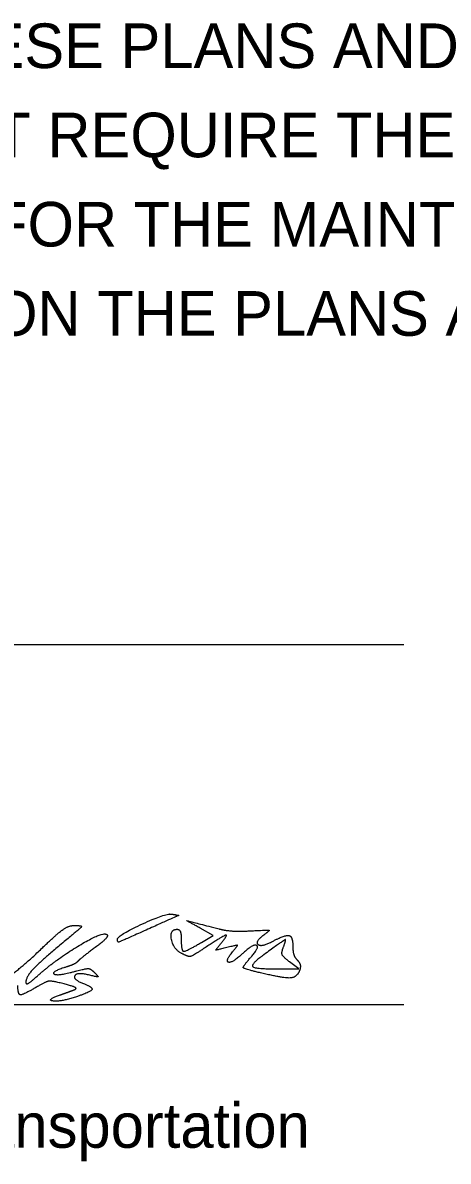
# Model space of a CAD drawing. Extents: x 0 to 34, y 0 to 22.
# Drawn here: x 26.833 to 28.167, y 7.305 to 10.877 of the extents above; entities that cross this region are included whole.
import ezdxf

# ---------------------------------------------------------------- set-up
doc = ezdxf.new("R2010")
doc.units = 0
doc.layers.add('SH_Data', color=7, linetype='Continuous')
doc.layers.add('SH_Text', color=7, linetype='Continuous')

msp = doc.modelspace()

# ---------------------------------------------------------------- linework, layer by layer
at = {"layer": 'SH_Data'}
for p, q in [((24.5279, 8.9262), (28.0279, 8.9262)), ((24.5279, 7.7968), (28.0279, 7.7968))]:
    msp.add_line(p, q, dxfattribs=at)
at = {"layer": 'SH_Text'}
for p, q in [((27.1295, 8.001), (27.1295, 8.001)), ((27.582, 7.8948), (27.582, 7.8948))]:
    msp.add_line(p, q, dxfattribs=at)
for points in [[(27.3933, 7.9914), (27.4297, 8.0129), (27.3889, 8.0359)], [(27.642, 7.9079), (27.6982, 7.908), (27.6695, 7.9301)]]:
    msp.add_lwpolyline(points, dxfattribs=at)
for points in [[(27.1295, 8.001), (27.1295, 8.0134), (27.2823, 8.0837), (27.3012, 8.08)], [(27.3012, 8.08), (27.3219, 8.076), (27.3226, 8.0764), (27.201, 8.0218)], [(26.8951, 7.9753), (26.9403, 8.019), (26.9774, 8.0447), (26.9951, 8.0444)], [(26.9951, 8.0444), (27.0194, 8.0439), (27.0156, 8.0375), (26.967, 7.9975)], [(27.3889, 8.0359), (27.3461, 8.06), (27.3452, 8.06), (27.4482, 8.0336)], [(26.8763, 7.8841), (26.93, 7.9329), (27.0769, 8.0229), (27.0938, 8.0172)], [(27.0938, 8.0172), (27.1022, 8.0144), (27.087, 7.9957), (27.0599, 7.9755)], [(27.201, 8.0218), (27.1385, 7.9937), (27.1295, 7.9911), (27.1295, 8.001)], [(27.3305, 7.9569), (27.304, 7.9711), (27.293, 8.0324), (27.317, 8.0324)], [(27.317, 8.0324), (27.3238, 8.0324), (27.3295, 8.0184), (27.3295, 8.0012)], [(27.4529, 7.9866), (27.4773, 8.0162), (27.4615, 8.0124), (27.4052, 7.9752)], [(27.4482, 8.0336), (27.4688, 8.0284), (27.5138, 8.0256), (27.5482, 8.0275)], [(27.5482, 8.0275), (27.6031, 8.0306), (27.608, 8.029), (27.5881, 8.0142)], [(27.5881, 8.0142), (27.5593, 7.9927), (27.5822, 7.9763), (27.6159, 7.9944)], [(27.6159, 7.9944), (27.6561, 8.0159), (27.6795, 8.0101), (27.6795, 7.9787)], [(26.7295, 7.8684), (26.7295, 7.8456), (26.8248, 7.907), (26.8951, 7.9753)], [(26.967, 7.9975), (26.8929, 7.9366), (26.842, 7.883), (26.842, 7.8663)], [(27.0599, 7.9755), (27.0328, 7.9553), (27.0079, 7.9353), (27.0045, 7.9311)], [(27.3295, 8.0012), (27.3295, 7.9644), (27.3438, 7.9622), (27.3933, 7.9914)], [(27.4052, 7.9752), (27.3652, 7.9487), (27.3519, 7.9454), (27.3305, 7.9569)], [(27.4723, 7.9749), (27.4392, 7.9667), (27.4374, 7.9678), (27.4529, 7.9866)], [(27.4924, 7.9642), (27.507, 7.9818), (27.5047, 7.983), (27.4723, 7.9749)], [(27.5462, 7.9428), (27.5767, 7.9764), (27.5551, 7.9874), (27.5211, 7.9554)], [(27.6497, 7.9756), (27.6596, 8.0014), (27.6514, 7.9983), (27.5888, 7.9527)], [(27.6695, 7.9301), (27.6491, 7.9458), (27.6434, 7.959), (27.6497, 7.9756)], [(27.6795, 7.9787), (27.6795, 7.9629), (27.6858, 7.9436), (27.6936, 7.9358)], [(27.0045, 7.9311), (27.001, 7.9268), (26.9856, 7.9194), (26.9701, 7.9145)], [(27.5211, 7.9554), (27.4892, 7.9255), (27.4661, 7.9325), (27.4924, 7.9642)], [(27.582, 7.8948), (27.5272, 7.9077), (27.5215, 7.9154), (27.5462, 7.9428)], [(27.5888, 7.9527), (27.5461, 7.9217), (27.5626, 7.9078), (27.642, 7.9079)], [(27.6936, 7.9358), (27.7014, 7.928), (27.7044, 7.9128), (27.7003, 7.902)], [(26.9701, 7.9145), (26.9206, 7.8991), (26.9401, 7.8854), (26.9919, 7.8992)], [(26.9919, 7.8992), (27.0302, 7.9095), (27.0455, 7.9089), (27.0575, 7.8966)], [(27.0575, 7.8966), (27.0702, 7.8837), (27.0666, 7.8823), (27.0388, 7.8892)], [(27.7003, 7.902), (27.6922, 7.8809), (27.651, 7.8784), (27.582, 7.8948)], [(26.842, 7.8663), (26.842, 7.8588), (26.8574, 7.8668), (26.8763, 7.8841)], [(26.9621, 7.8609), (26.9233, 7.8708), (26.9065, 7.8691), (26.8789, 7.8528)], [(26.992, 7.8417), (27.0034, 7.8458), (26.9917, 7.8533), (26.9621, 7.8609)], [(27.0388, 7.8892), (27.0021, 7.8982), (26.9889, 7.8751), (27.0232, 7.862)], [(27.0232, 7.862), (27.0538, 7.8502), (27.0449, 7.8353), (26.9981, 7.8199)], [(26.8789, 7.8528), (26.8339, 7.8262), (26.817, 7.8271), (26.817, 7.8559)], [(26.9981, 7.8199), (26.9515, 7.8045), (26.9042, 7.8102), (26.9482, 7.8259)], [(26.9482, 7.8259), (26.962, 7.8308), (26.9817, 7.8379), (26.992, 7.8417)]]:
    msp.add_open_spline(points, degree=2, dxfattribs=at)

# ---------------------------------------------------------------- texts
at = {"layer": 'SH_Data'}
for s, p in [(' I HEREBY APPROVE THESE PLANS AND DECLARE THAT THE MAKING OF THIS', (24.5279, 10.735)), ('IMPROVEMENT WILL NOT REQUIRE THE CLOSING TO TRAFFIC OF THE HIGHWAY', (24.5279, 10.455)), ('AND THAT PROVISIONS FOR THE MAINTENANCE AND SAFETY OF TRAFFIC', (24.5279, 10.175)), ('WILL BE AS SET FORTH ON THE PLANS AND ESTIMATES.', (24.5279, 9.895))]:
    msp.add_text(s, height=0.14, dxfattribs=at).set_placement(p)
at = {"layer": 'SH_Text'}
msp.add_text('Director, Department of Transportation', height=0.14, dxfattribs=at).set_placement((24.5279, 7.3468))

doc.saveas('drawing.dxf')
